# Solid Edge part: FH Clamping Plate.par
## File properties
Author: davee
Template: Normal.par
Last saved by: davee
Revision: 4
Application: Solid Edge
Accuracy: 0.990
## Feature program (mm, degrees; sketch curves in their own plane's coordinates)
sketch for "unnamed Protrusion 1" plane through (0, 0, 0) normal (0, 0, 1) x-axis (1, 0, 0)
  line (-130, -100) -> (130, -100)
  line (130, -100) -> (130, 100)
  line (130, 100) -> (-130, 100)
  line (-130, 100) -> (-130, -100)
  dimension (linear) = 130
  dimension (linear) = 130
extrude "unnamed Protrusion 1" add finite 29.5 along +normal
sketch for "Hole_1" plane through (0, 0, 29.5) normal (0, 0, 1) x-axis (1, 0, 0)
  hole centre (80, 49) bore radius 6.25
hole "Hole_1" diameter 12.5 through  CounterBoreDepth = 12.5 mm; VBottomAngle = 118 deg
sketch for "unnamed Hole 1" plane through (0, 0, 29.5) normal (0, 0, 1) x-axis (1, 0, 0)
  hole centre (80, -49) bore radius 6.25
hole "unnamed Hole 1" through
sketch for "unnamed Hole 2" plane through (0, 0, 29.5) normal (0, 0, 1) x-axis (1, 0, 0)
  hole centre (-80, -49) bore radius 6.25
hole "unnamed Hole 2" through
sketch for "unnamed Hole 3" plane through (0, 0, 29.5) normal (0, 0, 1) x-axis (1, 0, 0)
  hole centre (-80, 49) bore radius 6.25
hole "unnamed Hole 3" through
pattern "unnamed Pattern 1" of "Hole_1", "unnamed Hole 1", "unnamed Hole 2", "unnamed Hole 3"
sketch for "ExtrudedCutout_1" plane through (0, 0, 0) normal (0, 0, -1) x-axis (1, 0, 0)
  circle centre (0, 0) radius 19
extrude "ExtrudedCutout_1" cut finite 34.925 along -normal
sketch for "unnamed Cutout 1" plane through (0, 0, 29.5) normal (0, 0, 1) x-axis (-1, 0, 0)
extrude "unnamed Cutout 1" cut through along -normal
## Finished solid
Body 1: solid body, 20 faces, 32 edges, 8 vertices.
  Faces by surface: cylinder 10, plane 10
  Edges by curve: circle 20, line 12
Bounding box of the edges (mm): 260.000 x 200.000 x 29.500, from (-130, -100, 0) to (130, 100, 29.5).
Cylindrical faces by radius (mm): R3 x1, R6.25 x4, R9.5 x4, R19 x1
Planar faces by outward normal: +x 1, +y 1, +z 5, -x 1, -y 1, -z 1
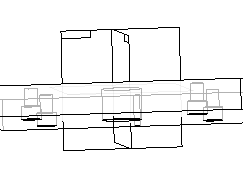
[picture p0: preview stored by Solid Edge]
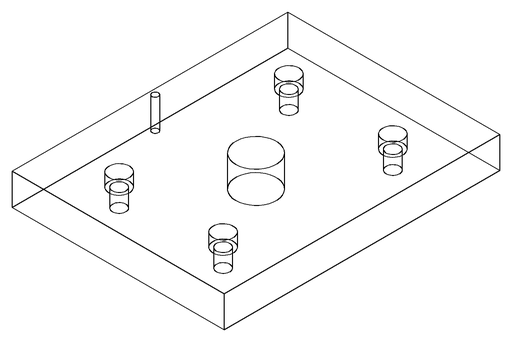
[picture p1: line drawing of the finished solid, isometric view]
